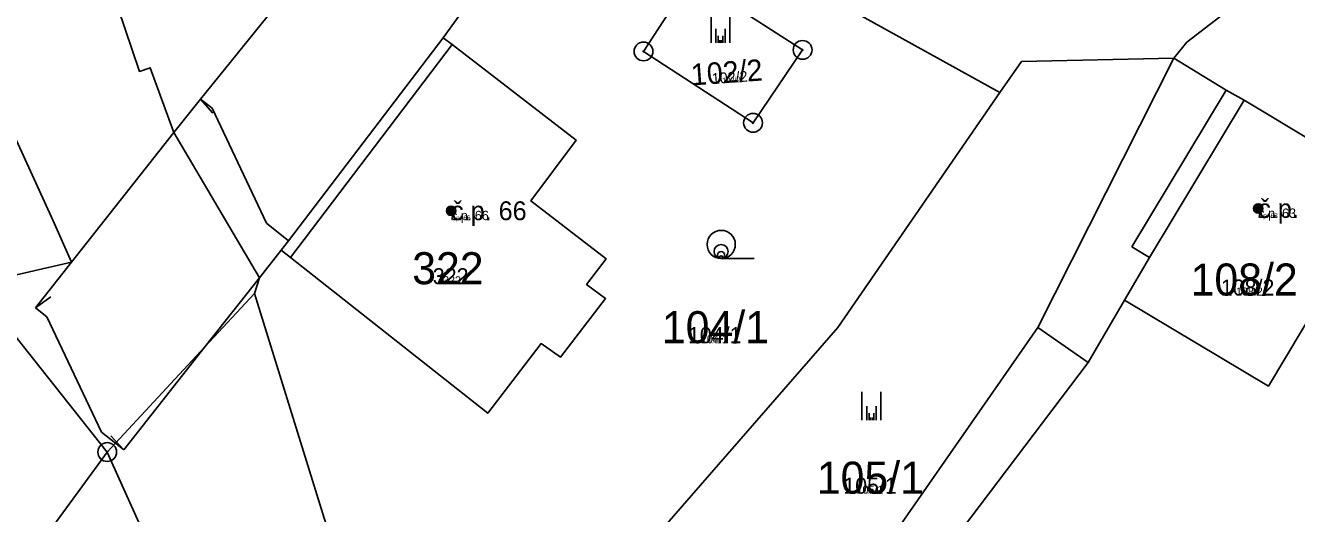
# Model space of a CAD drawing. Extents: x -744652 to -739090, y -980828 to -975855.
# Drawn here: x -742751.7 to -742684.2, y -978697.6 to -978671.7 of the extents above; entities that cross this region are included whole.
import ezdxf

# ---------------------------------------------------------------- set-up
doc = ezdxf.new("R2010")
doc.units = 0
for name, color, linetype in [('KAT_02_hranice parcel', 7, 'Continuous'), ('KAT_03_1000_st čísla parcelní', 7, 'Continuous'), ('KAT_03_1000_čísla parcelní', 7, 'Continuous'), ('KAT_03_1000_čísla popisná', 7, 'Continuous'), ('KAT_03_100_st čísla parcelní', 7, 'Continuous'), ('KAT_03_100_čísla parcelní', 7, 'Continuous'), ('KAT_03_100_čísla popisná', 7, 'Continuous'), ('KAT_03_250_st čísla parcelní', 7, 'Continuous'), ('KAT_03_250_čísla parcelní', 7, 'Continuous'), ('KAT_03_250_čísla popisná', 7, 'Continuous'), ('KAT_03_500_st čísla parcelní', 7, 'Continuous'), ('KAT_03_500_čísla parcelní', 7, 'Continuous'), ('KAT_03_500_čísla popisná', 7, 'Continuous'), ('KAT_04_vnitřní kresba', 7, 'Continuous'), ('KAT_05_1000_značky kultur', 7, 'Continuous'), ('KAT_05_100_značky kultur', 7, 'Continuous'), ('KAT_05_250_značky kultur', 7, 'Continuous'), ('KAT_05_500_značky kultur', 7, 'Continuous'), ('KAT_07_1000_značky budov', 7, 'Continuous'), ('KAT_07_100_značky budov', 7, 'Continuous'), ('KAT_07_500_značky budov', 7, 'Continuous'), ('KAT_11_značky bodu BP', 7, 'Continuous'), ('KAT_14_plocha_budovy', 7, 'Continuous')]:
    doc.layers.add(name, color=color, linetype=linetype)

msp = doc.modelspace()

# ---------------------------------------------------------------- linework, layer by layer
at = {"layer": 'KAT_02_hranice parcel'}
for p, q in [((-742699.91, -978675.21), (-742722.68, -978662.6)), ((-742724.73, -978665.7), (-742729.47, -978672.3)), ((-742690.67, -978673.38), (-742697.89, -978687.69)), ((-742743.78, -978677.33), (-742739.24, -978685.05)), ((-742738.08, -978683.58), (-742739.24, -978685.05)), ((-742754.39, -978685.4), (-742747.32, -978694.3)), ((-742739.24, -978685.05), (-742739.5, -978685.89)), ((-742697.89, -978687.69), (-742695.23, -978689.55)), ((-742747.32, -978694.3), (-742755.86, -978705.99))]:
    msp.add_line(p, q, dxfattribs=at)
for points in [[(-742746.65, -978653.52), (-742747.44, -978659.88), (-742748.66, -978665.08), (-742745.61, -978674.09), (-742745.04, -978673.9), (-742743.78, -978677.33)], [(-742743.78, -978677.33), (-742742.37, -978675.56), (-742738.84, -978671.22), (-742731.56, -978660.52), (-742729.75, -978657.77)], [(-742724.73, -978665.7), (-742717.25, -978670.59), (-742718.84, -978673.03), (-742713.02, -978676.82), (-742710.39, -978672.95), (-742723.81, -978664.33)], [(-742690.67, -978673.38), (-742689.98, -978672.54), (-742684.1, -978668)], [(-742754.39, -978685.4), (-742749.22, -978684.22), (-742750.19, -978682.03), (-742754.84, -978671.87)], [(-742738.08, -978683.58), (-742737.58, -978683.97), (-742727.11, -978692.24), (-742724.28, -978688.54), (-742723.25, -978689.27), (-742720.85, -978686.15), (-742721.86, -978685.4), (-742720.83, -978684.04), (-742724.82, -978680.97), (-742722.41, -978677.75), (-742729, -978672.67), (-742729.47, -978672.3)], [(-742729.47, -978672.3), (-742737.69, -978683.09), (-742738.08, -978683.58)], [(-742699.91, -978675.21), (-742698.77, -978673.57), (-742690.67, -978673.38)], [(-742695.23, -978689.55), (-742693.3, -978686.23), (-742685.65, -978690.8), (-742679.31, -978680.21), (-742686.93, -978675.62), (-742687.89, -978675.08), (-742690.67, -978673.38)], [(-742713.35, -978706.43), (-742719.63, -978700.45), (-742708.52, -978687.68), (-742699.91, -978675.21)], [(-742747.32, -978694.3), (-742746.88, -978693.83), (-742742.14, -978688.72), (-742739.5, -978685.89)], [(-742739.5, -978685.89), (-742733.11, -978706.48), (-742731.87, -978708.59), (-742727.85, -978720.17)], [(-742713.35, -978706.43), (-742711.87, -978707.76), (-742697.89, -978687.69)], [(-742706.48, -978712.13), (-742710.11, -978709.2), (-742695.23, -978689.55)], [(-742727.43, -978738.8), (-742733.97, -978723.94), (-742747.32, -978694.3)]]:
    msp.add_lwpolyline(points, dxfattribs=at)
at = {"layer": 'KAT_03_1000_čísla popisná'}
for centre in [(-742729.06, -978681.49), (-742729.06, -978681.49), (-742686.19, -978681.37), (-742686.19, -978681.37)]:
    msp.add_circle(centre, 0.25, dxfattribs=at)
at = {"layer": 'KAT_03_100_čísla popisná'}
for centre in [(-742686.19, -978681.37), (-742686.19, -978681.37), (-742729.06, -978681.49), (-742729.06, -978681.49)]:
    msp.add_circle(centre, 0.025, dxfattribs=at)
at = {"layer": 'KAT_03_250_čísla popisná'}
for centre in [(-742686.19, -978681.37), (-742686.19, -978681.37), (-742729.06, -978681.49), (-742729.06, -978681.49)]:
    msp.add_circle(centre, 0.0625, dxfattribs=at)
at = {"layer": 'KAT_03_500_čísla popisná'}
for centre in [(-742729.06, -978681.49), (-742729.06, -978681.49), (-742686.19, -978681.37), (-742686.19, -978681.37)]:
    msp.add_circle(centre, 0.125, dxfattribs=at)
at = {"layer": 'KAT_04_vnitřní kresba'}
for p, q in [((-742729, -978672.67), (-742737.58, -978683.97)), ((-742692.91, -978683.41), (-742687.89, -978675.08)), ((-742741.75, -978676.05), (-742742.37, -978675.56)), ((-742741.714, -978676.315), (-742742.37, -978675.561)), ((-742686.93, -978675.62), (-742691.97, -978683.98)), ((-742738.86, -978682.15), (-742741.75, -978676.05)), ((-742749.22, -978684.22), (-742743.78, -978677.33)), ((-742737.69, -978683.09), (-742738.86, -978682.15)), ((-742691.97, -978683.98), (-742693.3, -978686.23)), ((-742692.91, -978683.41), (-742691.97, -978683.98)), ((-742751.13, -978686.64), (-742749.22, -978684.22)), ((-742742.14, -978688.72), (-742739.24, -978685.05)), ((-742750.32, -978686.052), (-742751.129, -978686.64)), ((-742751.13, -978686.64), (-742750.52, -978687.12)), ((-742750.52, -978687.12), (-742747.62, -978693.25)), ((-742746.44, -978694.18), (-742742.14, -978688.72)), ((-742747.62, -978693.25), (-742746.88, -978693.83)), ((-742747.122, -978693.448), (-742746.44, -978694.179)), ((-742746.88, -978693.83), (-742746.44, -978694.18))]:
    msp.add_line(p, q, dxfattribs=at)
at = {"layer": 'KAT_05_1000_značky kultur'}
for p, q in [((-742715.251, -978672.58), (-742715.251, -978671.08)), ((-742714.25, -978672.58), (-742714.25, -978671.08)), ((-742714.713, -978684.03), (-742712.963, -978684.03)), ((-742707.241, -978692.61), (-742707.241, -978691.11)), ((-742706.24, -978692.61), (-742706.24, -978691.11))]:
    msp.add_line(p, q, dxfattribs=at)
msp.add_circle((-742714.713, -978683.28), 0.75, dxfattribs=at)
at = {"layer": 'KAT_05_100_značky kultur'}
for p, q in [((-742714.791, -978672.58), (-742714.791, -978672.43)), ((-742714.691, -978672.58), (-742714.691, -978672.43)), ((-742714.719, -978684.03), (-742714.544, -978684.03)), ((-742706.781, -978692.61), (-742706.781, -978692.46)), ((-742706.681, -978692.61), (-742706.681, -978692.46))]:
    msp.add_line(p, q, dxfattribs=at)
msp.add_circle((-742714.719, -978683.955), 0.075, dxfattribs=at)
at = {"layer": 'KAT_05_250_značky kultur'}
for p, q in [((-742714.868, -978672.58), (-742714.868, -978672.205)), ((-742714.618, -978672.58), (-742714.618, -978672.205)), ((-742714.718, -978684.03), (-742714.281, -978684.03)), ((-742706.858, -978692.61), (-742706.858, -978692.235)), ((-742706.608, -978692.61), (-742706.608, -978692.235))]:
    msp.add_line(p, q, dxfattribs=at)
msp.add_circle((-742714.718, -978683.842), 0.187, dxfattribs=at)
at = {"layer": 'KAT_05_500_značky kultur'}
for p, q in [((-742714.995, -978672.58), (-742714.995, -978671.83)), ((-742714.495, -978672.58), (-742714.495, -978671.83)), ((-742714.716, -978684.03), (-742713.841, -978684.03)), ((-742706.986, -978692.61), (-742706.986, -978691.86)), ((-742706.485, -978692.61), (-742706.485, -978691.86))]:
    msp.add_line(p, q, dxfattribs=at)
msp.add_circle((-742714.716, -978683.655), 0.375, dxfattribs=at)
at = {"layer": 'KAT_07_1000_značky budov'}
for centre in [(-742729.067, -978681.489), (-742686.197, -978681.369)]:
    msp.add_circle(centre, 0.175, dxfattribs=at)
at = {"layer": 'KAT_07_100_značky budov'}
for centre in [(-742686.191, -978681.37), (-742729.061, -978681.49)]:
    msp.add_circle(centre, 0.0175, dxfattribs=at)
at = {"layer": 'KAT_07_500_značky budov'}
for centre, radius in [((-742686.193, -978681.37), 0.0875), ((-742686.192, -978681.37), 0.0438), ((-742729.063, -978681.49), 0.0875), ((-742729.062, -978681.49), 0.0438)]:
    msp.add_circle(centre, radius, dxfattribs=at)
at = {"layer": 'KAT_11_značky bodu BP'}
for centre, radius in [((-742718.84, -978673.03), 0.5), ((-742710.39, -978672.95), 0.5), ((-742718.84, -978673.03), 0.0303), ((-742710.39, -978672.95), 0.0303), ((-742713.02, -978676.82), 0.5), ((-742713.02, -978676.82), 0.0303), ((-742747.32, -978694.3), 0.5), ((-742747.32, -978694.3), 0.0303)]:
    msp.add_circle(centre, radius, dxfattribs=at)
at = {"layer": 'KAT_14_plocha_budovy'}
for points in [[(-742729, -978672.67), (-742737.58, -978683.97), (-742727.11, -978692.24), (-742724.28, -978688.54), (-742723.25, -978689.27), (-742720.85, -978686.15), (-742721.86, -978685.4), (-742720.83, -978684.04), (-742724.82, -978680.97), (-742722.41, -978677.75)], [(-742691.97, -978683.98), (-742693.3, -978686.23), (-742685.65, -978690.8), (-742679.31, -978680.21), (-742686.93, -978675.62)]]:
    msp.add_lwpolyline(points, close=True, dxfattribs=at)

# ---------------------------------------------------------------- texts
at = {"layer": 'KAT_03_1000_st čísla parcelní'}
for s, p in [('322', (-742731.124, -978685.39)), ('108/2', (-742689.783, -978685.99))]:
    msp.add_text(s, height=1.7, dxfattribs=at).set_placement(p)
at = {"layer": 'KAT_03_1000_čísla parcelní'}
msp.add_text('102/2', height=1.14, rotation=4, dxfattribs=at).set_placement((-742716.285, -978674.838))
for s, p in [('104/1', (-742717.863, -978688.52)), ('105/1', (-742709.633, -978696.51))]:
    msp.add_text(s, height=1.7, dxfattribs=at).set_placement(p)
at = {"layer": 'KAT_03_1000_čísla popisná'}
for s, height, p in [('č.p. 66', 1, (-742729.06, -978681.99)), ('č.p. 63', 1, (-742686.19, -978681.87)), ('322', 0.017, (-742728.957, -978685.39)), ('108/2', 0.017, (-742686.603, -978685.99))]:
    msp.add_text(s, height=height, dxfattribs=at).set_placement(p)
at = {"layer": 'KAT_03_100_st čísla parcelní'}
for s, p in [('322', (-742729.154, -978685.39)), ('108/2', (-742686.892, -978685.99))]:
    msp.add_text(s, height=0.17, dxfattribs=at).set_placement(p)
at = {"layer": 'KAT_03_100_čísla parcelní'}
msp.add_text('102/2', height=0.114, rotation=4, dxfattribs=at).set_placement((-742714.323, -978674.701))
for s, p in [('104/1', (-742715.376, -978688.52)), ('105/1', (-742707.103, -978696.51))]:
    msp.add_text(s, height=0.17, dxfattribs=at).set_placement(p)
at = {"layer": 'KAT_03_100_čísla popisná'}
for s, height, p in [('č.p. 66', 0.1, (-742729.06, -978681.99)), ('č.p. 63', 0.1, (-742686.19, -978681.87)), ('322', 0.0017, (-742728.938, -978685.39)), ('108/2', 0.0017, (-742686.574, -978685.99))]:
    msp.add_text(s, height=height, dxfattribs=at).set_placement(p)
at = {"layer": 'KAT_03_250_st čísla parcelní'}
for s, p in [('322', (-742729.483, -978685.39)), ('108/2', (-742687.374, -978685.99))]:
    msp.add_text(s, height=0.425, dxfattribs=at).set_placement(p)
at = {"layer": 'KAT_03_250_čísla parcelní'}
msp.add_text('102/2', height=0.285, rotation=4, dxfattribs=at).set_placement((-742714.65, -978674.724))
for s, p in [('104/1', (-742715.79, -978688.52)), ('105/1', (-742707.525, -978696.51))]:
    msp.add_text(s, height=0.425, dxfattribs=at).set_placement(p)
at = {"layer": 'KAT_03_250_čísla popisná'}
for s, height, p in [('č.p. 66', 0.25, (-742729.06, -978681.99)), ('č.p. 63', 0.25, (-742686.19, -978681.87)), ('322', 0.00425, (-742728.941, -978685.39)), ('108/2', 0.00425, (-742686.579, -978685.99))]:
    msp.add_text(s, height=height, dxfattribs=at).set_placement(p)
at = {"layer": 'KAT_03_500_st čísla parcelní'}
for s, p in [('322', (-742730.03, -978685.39)), ('108/2', (-742688.177, -978685.99))]:
    msp.add_text(s, height=0.85, dxfattribs=at).set_placement(p)
at = {"layer": 'KAT_03_500_čísla parcelní'}
msp.add_text('102/2', height=0.57, rotation=4, dxfattribs=at).set_placement((-742715.195, -978674.762))
for s, p in [('104/1', (-742716.481, -978688.52)), ('105/1', (-742708.228, -978696.51))]:
    msp.add_text(s, height=0.85, dxfattribs=at).set_placement(p)
at = {"layer": 'KAT_03_500_čísla popisná'}
for s, height, p in [('č.p. 63', 0.5, (-742686.19, -978681.87)), ('č.p. 66', 0.5, (-742729.06, -978681.99)), ('322', 0.0085, (-742728.946, -978685.39)), ('108/2', 0.0085, (-742686.587, -978685.99))]:
    msp.add_text(s, height=height, dxfattribs=at).set_placement(p)

doc.saveas('drawing.dxf')
